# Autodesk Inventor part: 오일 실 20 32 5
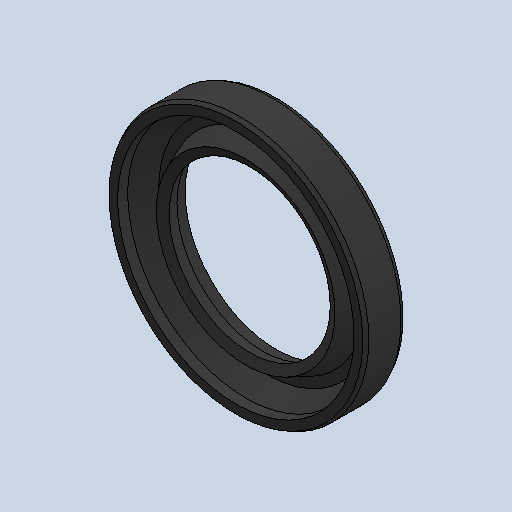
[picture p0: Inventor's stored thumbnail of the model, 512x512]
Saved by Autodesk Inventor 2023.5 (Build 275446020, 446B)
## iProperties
Created: 2026-07
Part Number: 오일 실 20 32 5
Material: 고무
Description: 오일 실 - 스프링 장착, 비스프링, 고무 덮개 G
Document SubType Name: Modeling
Designer: 1강의실14
Density: 0.93 g/cm^3
Appearance: 기본값
Author: jhkim
Sending System: Autodesk Inventor 2027
Preprocessor: ST-DEVELOPER v20.1
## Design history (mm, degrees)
node "오일 실 20 32 51"
node "솔리드1"
body "Solid1"
